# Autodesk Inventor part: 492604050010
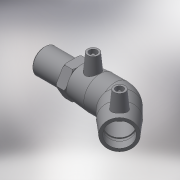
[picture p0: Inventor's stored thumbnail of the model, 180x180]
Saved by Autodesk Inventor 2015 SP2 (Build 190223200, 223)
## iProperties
Created: 2017-06
Part Number: 492604050010
Material: Generic
Description: PLASSON 45° ELBOW TRANSITION MALE 50-1"
Document SubType Name: Modeling
Designer: KIM
Mass: 291.537 g
Surface Area: 605.812 cm^2
Volume: 291.537 cm^3
Density: 1 g/cm^3
Appearance: Default
Author: KIM
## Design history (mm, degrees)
derived "492604.ipt"
feature "Solid1::492604.ipt"
tag "TaggingFeature1"
body "Solid1"
other parameters: "d2" = 67, "d4" = 31.75, "d5" = 60.3, "d8" = 168 deg, "d10" = 19.6, "d11" = 6.53333, "d29" = 51, "d30" = 15, "d31" = 44.45, "d34" = 5 deg, "d41" = 4, "d42" = 14, "d43" = 0, "d50" = 32.5, "d51" = 19.6, "d52" = 50.47, "d54" = 135 deg, "d86" = 30.15, "d87" = 135 deg, "d88" = 127, "d90" = 49, "d91" = 0, "d92" = 49, "d93" = 0, "d101" = 3, "d102" = 0, "d107" = 0.1, "d108" = 38, "d109" = 33.249, "d110" = 34, "d111" = 8.5, "d112" = 67, "d113" = 23.2743, "d114" = 30.6, "d116" = 2.01, "d122" = 0, "d123" = 1.66245, "L_" = 161, "L_1" = 49, "D_" = 38, "A_" = 51, "d_2" = 12, "L_2" = 34, "R_" = 33.249, "D_1" = 67
